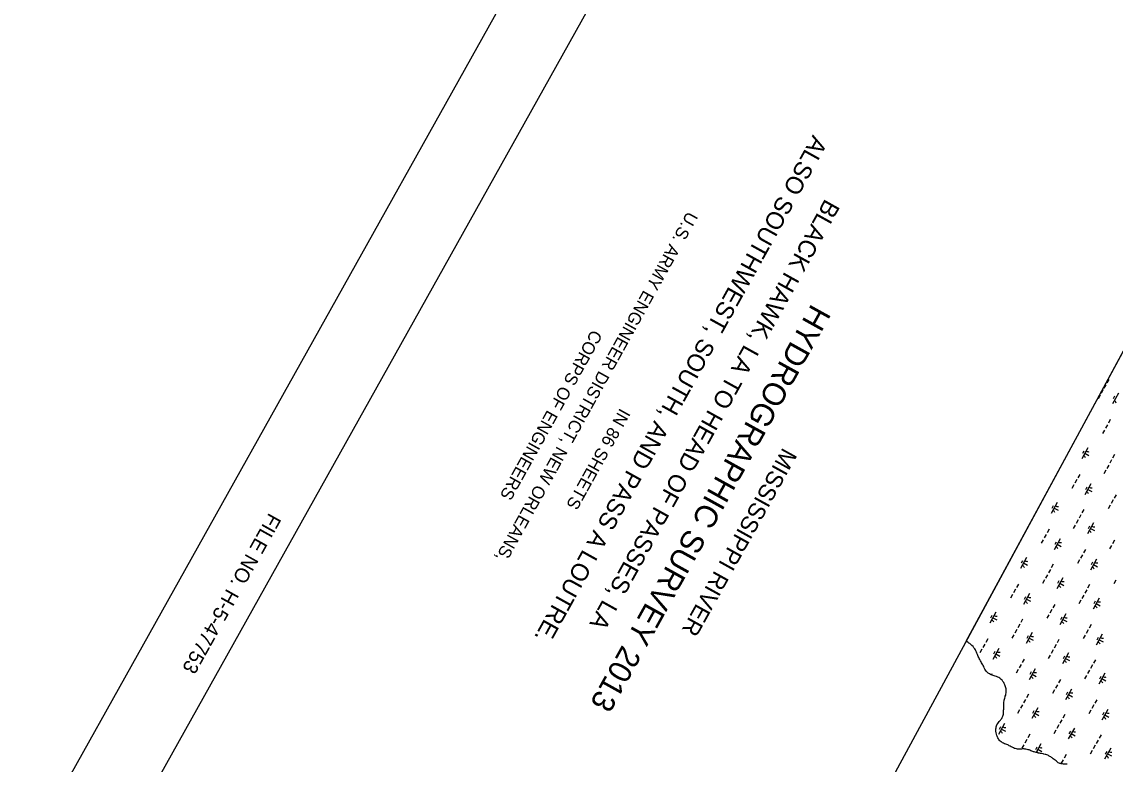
# Model space of a CAD drawing. Extents: x 3923531 to 3943530, y 207391 to 229799.
# Drawn here: x 3923785 to 3928152, y 213929 to 216895 of the extents above; entities that cross this region are included whole.
import ezdxf

# ---------------------------------------------------------------- set-up
doc = ezdxf.new("R2010")
doc.units = 0
for name, color, linetype in [('G-ANNO-NPLT', 7, 'Continuous'), ('V-ANNO-SYMB', 7, 'Continuous'), ('V-ANNO-TEXT', 7, 'Continuous'), ('V-GRID-FRAM', 7, 'Continuous'), ('V-WETL-SWMP', 7, 'Continuous')]:
    doc.layers.add(name, color=color, linetype=linetype)

msp = doc.modelspace()

# ---------------------------------------------------------------- linework, layer by layer
at = {"layer": 'G-ANNO-NPLT'}
msp.add_lwpolyline([(3932726.7, 229544.3), (3923785.3, 213539.2), (3934334.2, 207646), (3943275.5, 223651.2)], close=True, dxfattribs=at)
at = {"layer": 'V-ANNO-SYMB'}
msp.add_lwpolyline([(3932328.9, 228191.4), (3924261.4, 213750.5), (3934264.5, 208162.2), (3942332, 222603.1), (3932328.9, 228191.4)], dxfattribs=at)
at = {"layer": 'V-GRID-FRAM'}
msp.add_lwpolyline([(3941569.4, 222286.8), (3934196.5, 209089.1), (3926890.1, 213186.2), (3934009.8, 226348.1), (3941569.4, 222286.8)], dxfattribs=at)
at = {"layer": 'V-WETL-SWMP'}
for p, q in [((3927557.6, 214420.2), (3930423.1, 219717.6)), ((3928127.1, 215466.1), (3928119.3, 215452.1)), ((3928103.7, 215424.2), (3928095.9, 215410.2)), ((3928115.4, 215445.1), (3928107.6, 215431.2)), ((3928092, 215403.2), (3928084.2, 215389.3)), ((3928165.6, 215412), (3928141.3, 215368.3)), ((3928149.6, 215399.2), (3928143.8, 215388.7)), ((3928133, 215305.9), (3928125.2, 215292)), ((3928109.6, 215264), (3928101.8, 215250.1)), ((3928121.3, 215285), (3928113.5, 215271)), ((3928043.2, 215192.9), (3928018.9, 215149.3)), ((3928027.2, 215180.1), (3928021.4, 215169.6)), ((3928031.1, 215171.1), (3928046.8, 215162.3)), ((3928149.9, 215165.9), (3928142.1, 215151.9)), ((3928126.5, 215124), (3928118.7, 215110)), ((3928138.2, 215144.9), (3928130.4, 215131)), ((3928010.6, 215086.8), (3928002.8, 215072.9)), ((3928114.8, 215103), (3928107, 215089.1)), ((3927987.2, 215044.9), (3927979.4, 215031)), ((3927998.9, 215065.9), (3927991.1, 215051.9)), ((3928055.3, 215048.5), (3928030.9, 215004.8)), ((3928039.3, 215035.6), (3928033.4, 215025.2)), ((3928043.1, 215026.6), (3928058.8, 215017.9)), ((3928144.1, 214984.8), (3928136.3, 214970.8)), ((3928155.8, 215005.7), (3928148, 214991.7)), ((3927920.9, 214973.8), (3927896.5, 214930.2)), ((3927904.9, 214961), (3927899, 214950.5)), ((3927908.7, 214952), (3927924.4, 214943.2)), ((3928027.5, 214946.8), (3928019.7, 214932.8)), ((3928132.4, 214963.8), (3928124.6, 214949.8)), ((3928004.1, 214904.9), (3927996.3, 214890.9)), ((3928015.8, 214925.8), (3928008, 214911.9)), ((3927888.2, 214867.8), (3927880.4, 214853.8)), ((3927992.4, 214883.9), (3927984.6, 214870)), ((3928066.1, 214892.7), (3928041.7, 214849.1)), ((3928050.1, 214879.9), (3928044.2, 214869.4)), ((3928053.9, 214870.9), (3928069.6, 214862.1)), ((3927864.8, 214825.9), (3927857, 214811.9)), ((3927876.5, 214846.8), (3927868.7, 214832.8)), ((3927932.9, 214829.4), (3927908.5, 214785.7)), ((3927916.9, 214816.6), (3927911, 214806.1)), ((3928149.3, 214823.8), (3928141.5, 214809.8)), ((3927920.7, 214807.6), (3927936.4, 214798.8)), ((3928021.7, 214765.7), (3928013.9, 214751.7)), ((3928033.4, 214786.6), (3928025.6, 214772.7)), ((3928137.6, 214802.8), (3928129.8, 214788.8)), ((3927798.5, 214754.7), (3927774.1, 214711.1)), ((3927782.5, 214741.9), (3927776.6, 214731.4)), ((3927786.3, 214732.9), (3927802, 214724.1)), ((3927905.1, 214727.7), (3927897.3, 214713.7)), ((3928010, 214744.7), (3928002.2, 214730.8)), ((3928078.1, 214748.3), (3928053.7, 214704.6)), ((3928062.1, 214735.4), (3928056.2, 214725)), ((3928065.9, 214726.4), (3928081.6, 214717.7)), ((3927881.7, 214685.8), (3927873.9, 214671.8)), ((3927893.4, 214706.8), (3927885.6, 214692.8)), ((3927765.8, 214648.7), (3927758, 214634.7)), ((3927870, 214664.9), (3927862.2, 214650.9)), ((3927943.7, 214673.6), (3927919.3, 214630)), ((3927927.7, 214660.8), (3927921.8, 214650.3)), ((3927931.5, 214651.8), (3927947.2, 214643)), ((3928050.3, 214646.6), (3928042.5, 214632.6)), ((3928155.2, 214663.6), (3928147.4, 214649.6)), ((3927742.4, 214606.8), (3927734.6, 214592.8)), ((3927754.1, 214627.7), (3927746.3, 214613.7)), ((3927810.5, 214610.3), (3927786.1, 214566.7)), ((3927794.5, 214597.5), (3927788.6, 214587)), ((3928026.9, 214604.7), (3928019.1, 214590.7)), ((3928038.6, 214625.6), (3928030.8, 214611.7)), ((3928088.9, 214592.5), (3928064.5, 214548.8)), ((3927798.3, 214588.5), (3927814, 214579.7)), ((3927899.3, 214546.6), (3927891.5, 214532.6)), ((3927911, 214567.5), (3927903.2, 214553.6)), ((3928015.2, 214583.7), (3928007.4, 214569.8)), ((3928072.9, 214579.7), (3928067, 214569.2)), ((3928076.7, 214570.7), (3928092.4, 214561.9)), ((3927676.1, 214535.7), (3927651.7, 214492)), ((3927660.1, 214522.8), (3927654.2, 214512.4)), ((3927663.9, 214513.8), (3927679.6, 214505.1)), ((3927782.7, 214508.6), (3927774.9, 214494.7)), ((3927887.6, 214525.6), (3927879.8, 214511.7)), ((3927955.7, 214529.2), (3927931.3, 214485.5)), ((3927939.7, 214516.4), (3927933.8, 214505.9)), ((3927943.5, 214507.4), (3927959.2, 214498.6)), ((3927759.3, 214466.7), (3927751.5, 214452.8)), ((3927771, 214487.7), (3927763.2, 214473.7)), ((3928044.5, 214465.5), (3928036.7, 214451.5)), ((3928056.2, 214486.4), (3928048.4, 214472.5)), ((3927559.2, 214418.9), (3927557.6, 214420.2)), ((3927561.7, 214417.1), (3927559.2, 214418.9)), ((3927565.1, 214414.7), (3927561.7, 214417.1)), ((3927643.4, 214429.6), (3927635.6, 214415.6)), ((3927747.6, 214445.8), (3927739.8, 214431.8)), ((3927821.3, 214454.5), (3927796.9, 214410.9)), ((3927805.3, 214441.7), (3927799.4, 214431.2)), ((3927809.1, 214432.7), (3927824.8, 214423.9)), ((3927927.9, 214427.5), (3927920.1, 214413.5)), ((3928032.8, 214444.5), (3928025, 214430.5)), ((3928100.9, 214448.1), (3928076.5, 214404.4)), ((3928084.9, 214435.2), (3928079, 214424.8)), ((3928088.7, 214426.2), (3928104.4, 214417.5)), ((3927567.9, 214412.9), (3927565.1, 214414.7)), ((3927571.8, 214410.4), (3927567.9, 214412.9)), ((3927576.2, 214406.9), (3927571.8, 214410.4)), ((3927579.4, 214403.5), (3927576.2, 214406.9)), ((3927584.5, 214398.4), (3927579.4, 214403.5)), ((3927586.6, 214396), (3927584.5, 214398.4)), ((3927588.4, 214393.5), (3927586.6, 214396)), ((3927591.2, 214389.9), (3927588.4, 214393.5)), ((3927594.2, 214385.2), (3927591.2, 214389.9)), ((3927596, 214381.5), (3927594.2, 214385.2)), ((3927598.6, 214376.5), (3927596, 214381.5)), ((3927600.1, 214372.7), (3927598.6, 214376.5)), ((3927602.1, 214367.3), (3927600.1, 214372.7)), ((3927620, 214387.7), (3927612.2, 214373.7)), ((3927631.7, 214408.6), (3927623.9, 214394.7)), ((3927688.1, 214391.2), (3927663.7, 214347.6)), ((3927672.1, 214378.4), (3927666.2, 214367.9)), ((3927904.5, 214385.6), (3927896.7, 214371.6)), ((3927916.2, 214406.5), (3927908.4, 214392.6)), ((3927966.5, 214373.4), (3927942.1, 214329.8)), ((3927603.6, 214363.7), (3927602.1, 214367.3)), ((3927605.4, 214359.2), (3927603.6, 214363.7)), ((3927607.2, 214355.7), (3927605.4, 214359.2)), ((3927609.6, 214351.2), (3927607.2, 214355.7)), ((3927611.6, 214347.7), (3927609.6, 214351.2)), ((3927613.6, 214343.9), (3927611.6, 214347.7)), ((3927615.1, 214341.3), (3927613.6, 214343.9)), ((3927617, 214337.9), (3927615.1, 214341.3)), ((3927619, 214333.9), (3927617, 214337.9)), ((3927621.5, 214329.7), (3927619, 214333.9)), ((3927623.4, 214326.1), (3927621.5, 214329.7)), ((3927675.9, 214369.4), (3927691.6, 214360.6)), ((3927776.9, 214327.5), (3927769.1, 214313.5)), ((3927788.6, 214348.5), (3927780.8, 214334.5)), ((3927892.8, 214364.6), (3927885, 214350.7)), ((3927950.5, 214360.6), (3927944.6, 214350.1)), ((3927954.3, 214351.6), (3927970, 214342.8)), ((3928073.2, 214346.4), (3928065.4, 214332.4)), ((3927624.9, 214323.5), (3927623.4, 214326.1)), ((3927627.2, 214318.6), (3927624.9, 214323.5)), ((3927628.9, 214314.4), (3927627.2, 214318.6)), ((3927630.4, 214311.7), (3927628.9, 214314.4)), ((3927632.4, 214307.9), (3927630.4, 214311.7)), ((3927634.6, 214304.4), (3927632.4, 214307.9)), ((3927637.3, 214300.9), (3927634.6, 214304.4)), ((3927639.5, 214298.3), (3927637.3, 214300.9)), ((3927642.4, 214295.1), (3927639.5, 214298.3)), ((3927645, 214292.9), (3927642.4, 214295.1)), ((3927647.7, 214291.3), (3927645, 214292.9)), ((3927651, 214289.5), (3927647.7, 214291.3)), ((3927654.4, 214287.4), (3927651, 214289.5)), ((3927657.5, 214286), (3927654.4, 214287.4)), ((3927661.4, 214284.4), (3927657.5, 214286)), ((3927660.3, 214289.5), (3927658.2, 214285.7)), ((3927664.8, 214283), (3927661.4, 214284.4)), ((3927765.2, 214306.6), (3927757.4, 214292.6)), ((3927833.3, 214310.1), (3927808.9, 214266.4)), ((3927817.3, 214297.3), (3927811.4, 214286.8)), ((3927821.1, 214288.3), (3927836.8, 214279.5)), ((3928049.8, 214304.5), (3928041.9, 214290.5)), ((3928061.5, 214325.4), (3928053.7, 214311.5)), ((3928111.7, 214292.3), (3928087.3, 214248.6)), ((3927669.3, 214281.2), (3927664.8, 214283)), ((3927672.9, 214280.3), (3927669.3, 214281.2)), ((3927677.7, 214278.7), (3927672.9, 214280.3)), ((3927680.6, 214277.8), (3927677.7, 214278.7)), ((3927684, 214276.5), (3927680.6, 214277.8)), ((3927687.1, 214275.3), (3927684, 214276.5)), ((3927691.1, 214273.1), (3927687.1, 214275.3)), ((3927694.8, 214270), (3927691.1, 214273.1)), ((3927697.3, 214267.6), (3927694.8, 214270)), ((3927700.6, 214263.9), (3927697.3, 214267.6)), ((3927703.6, 214259.7), (3927700.6, 214263.9)), ((3927707.2, 214255), (3927703.6, 214259.7)), ((3927709.4, 214251.2), (3927707.2, 214255)), ((3927711.7, 214246.4), (3927709.4, 214251.2)), ((3927713.2, 214242.5), (3927711.7, 214246.4)), ((3927714.9, 214237.9), (3927713.2, 214242.5)), ((3927922.1, 214246.4), (3927914.3, 214232.4)), ((3927933.8, 214267.3), (3927926, 214253.4)), ((3928038, 214283.5), (3928030.2, 214269.6)), ((3928095.7, 214279.5), (3928089.9, 214269)), ((3928099.5, 214270.5), (3928115.2, 214261.7)), ((3927711, 214192.1), (3927712.4, 214197.3)), ((3927712.4, 214197.3), (3927713.5, 214200.9)), ((3927713.5, 214200.9), (3927715.3, 214205.1)), ((3927716, 214233.7), (3927714.9, 214237.9)), ((3927715.3, 214205.1), (3927716, 214208.7)), ((3927716.7, 214230.4), (3927716, 214233.7)), ((3927716, 214208.7), (3927716.8, 214214.1)), ((3927717.1, 214224.9), (3927716.7, 214230.4)), ((3927716.8, 214214.1), (3927717.1, 214221.7)), ((3927717.1, 214221.7), (3927717.1, 214224.9)), ((3927805.6, 214208.4), (3927797.8, 214194.4)), ((3927910.4, 214225.4), (3927902.6, 214211.5)), ((3927978.5, 214229), (3927954.1, 214185.3)), ((3927962.5, 214216.1), (3927956.7, 214205.7)), ((3927966.3, 214207.1), (3927982, 214198.4)), ((3927707, 214152.2), (3927707.4, 214156.9)), ((3927707.1, 214160.1), (3927707.4, 214165.5)), ((3927707.4, 214156.9), (3927707.1, 214160.1)), ((3927707.4, 214169.8), (3927707.8, 214172.9)), ((3927707.4, 214165.5), (3927707.4, 214169.8)), ((3927707.8, 214172.9), (3927708, 214176.5)), ((3927708, 214176.5), (3927709, 214181.8)), ((3927709, 214181.8), (3927709.5, 214185.2)), ((3927709.5, 214185.2), (3927710.2, 214188.2)), ((3927710.2, 214188.2), (3927711, 214192.1)), ((3927782.1, 214166.5), (3927774.3, 214152.5)), ((3927793.8, 214187.5), (3927786, 214173.5)), ((3927844.1, 214154.3), (3927819.7, 214110.7)), ((3928067.3, 214165.3), (3928059.5, 214151.3)), ((3928079, 214186.2), (3928071.2, 214172.2)), ((3927696.3, 214107.1), (3927699.1, 214111.8)), ((3927699.1, 214111.8), (3927701.2, 214115.8)), ((3927701.2, 214115.8), (3927703.3, 214120.6)), ((3927703.3, 214120.6), (3927704.8, 214124.7)), ((3927704.8, 214124.7), (3927705.8, 214128.8)), ((3927705.8, 214128.8), (3927706.4, 214133.3)), ((3927706.4, 214133.3), (3927706.5, 214136.5)), ((3927706.5, 214136.5), (3927706.9, 214141)), ((3927706.9, 214144.1), (3927707, 214148.6)), ((3927706.9, 214141), (3927706.9, 214144.1)), ((3927707, 214148.6), (3927707, 214152.2)), ((3927770.4, 214145.6), (3927762.6, 214131.6)), ((3927828.1, 214141.5), (3927822.2, 214131)), ((3927831.9, 214132.5), (3927847.6, 214123.7)), ((3927950.8, 214127.3), (3927943, 214113.3)), ((3928055.6, 214144.3), (3928047.8, 214130.3)), ((3928123.7, 214147.8), (3928099.3, 214104.2)), ((3928107.7, 214135), (3928101.9, 214124.5)), ((3928111.5, 214126), (3928127.2, 214117.2)), ((3927675.6, 214070.3), (3927676.4, 214073.6)), ((3927675.7, 214065.1), (3927675.6, 214070.3)), ((3927676.4, 214073.6), (3927677.3, 214078.2)), ((3927677.3, 214078.2), (3927678.2, 214081.5)), ((3927678.2, 214081.5), (3927680, 214085.9)), ((3927680, 214085.9), (3927683.1, 214091.2)), ((3927683.1, 214091.2), (3927685.8, 214095.3)), ((3927685.8, 214095.3), (3927688.4, 214098.9)), ((3927710.9, 214091), (3927686.5, 214047.4)), ((3927688.4, 214098.9), (3927690.5, 214101.3)), ((3927694.9, 214078.2), (3927689, 214067.7)), ((3927690.5, 214101.3), (3927693.8, 214104.3)), ((3927693.8, 214104.3), (3927696.3, 214107.1)), ((3927698.7, 214069.2), (3927714.4, 214060.4)), ((3927927.4, 214085.4), (3927919.6, 214071.4)), ((3927939.1, 214106.3), (3927931.3, 214092.4)), ((3927989.3, 214073.2), (3927964.9, 214029.5)), ((3927676.2, 214060.6), (3927675.7, 214065.1)), ((3927677.5, 214054.4), (3927676.2, 214060.6)), ((3927678.6, 214048.2), (3927677.5, 214054.4)), ((3927679.9, 214043.5), (3927678.6, 214048.2)), ((3927681.1, 214040.6), (3927679.9, 214043.5)), ((3927682.4, 214037.3), (3927681.1, 214040.6)), ((3927683.9, 214034.7), (3927682.4, 214037.3)), ((3927686.5, 214030), (3927683.9, 214034.7)), ((3927688, 214027.2), (3927686.5, 214030)), ((3927690.8, 214023.1), (3927688, 214027.2)), ((3927693.4, 214020.3), (3927690.8, 214023.1)), ((3927799.7, 214027.3), (3927791.9, 214013.3)), ((3927811.4, 214048.3), (3927803.6, 214034.3)), ((3927915.7, 214064.4), (3927907.8, 214050.5)), ((3927973.3, 214060.4), (3927967.5, 214049.9)), ((3927977.1, 214051.4), (3927992.8, 214042.6)), ((3928084.3, 214025.2), (3928076.5, 214011.2)), ((3928096, 214046.2), (3928088.2, 214032.2)), ((3927696.6, 214018.2), (3927693.4, 214020.3)), ((3927699.9, 214016.2), (3927696.6, 214018.2)), ((3927702.8, 214014.7), (3927699.9, 214016.2)), ((3927706, 214012.5), (3927702.8, 214014.7)), ((3927709.8, 214010.6), (3927706, 214012.5)), ((3927711.5, 214009.7), (3927709.8, 214010.6)), ((3927719.9, 214007), (3927711.5, 214009.7)), ((3927723.2, 214005.8), (3927719.9, 214007)), ((3927725.9, 214004.5), (3927723.2, 214005.8)), ((3927729.3, 214002.4), (3927725.9, 214004.5)), ((3927733.1, 214000.5), (3927729.3, 214002.4)), ((3927736.8, 213998.4), (3927733.1, 214000.5)), ((3927740.6, 213996.9), (3927736.8, 213998.4)), ((3927743.4, 213995.7), (3927740.6, 213996.9)), ((3927746.6, 213993.8), (3927743.4, 213995.7)), ((3927750.5, 213992), (3927746.6, 213993.8)), ((3927753.5, 213990.9), (3927750.5, 213992)), ((3927758.3, 213989.8), (3927753.5, 213990.9)), ((3927762.9, 213989.1), (3927758.3, 213989.8)), ((3927766.9, 213988.7), (3927762.9, 213989.1)), ((3927770.3, 213988.8), (3927766.9, 213988.7)), ((3927774.1, 213988.9), (3927770.3, 213988.8)), ((3927777.9, 213989.4), (3927774.1, 213988.9)), ((3927781.7, 213989.7), (3927777.9, 213989.4)), ((3927788, 214006.3), (3927780.2, 213992.4)), ((3927785.1, 213989.8), (3927781.7, 213989.7)), ((3927788.6, 213989.8), (3927785.1, 213989.8)), ((3927791.8, 213989.2), (3927788.6, 213989.8)), ((3927796.1, 213988.3), (3927791.8, 213989.2)), ((3927800.4, 213987.4), (3927796.1, 213988.3)), ((3927804.7, 213986.4), (3927800.4, 213987.4)), ((3927808.8, 213985.5), (3927804.7, 213986.4)), ((3927812.1, 213984.1), (3927808.8, 213985.5)), ((3927816, 213982.2), (3927812.1, 213984.1)), ((3927819.6, 213980.6), (3927816, 213982.2)), ((3927822.9, 213979.3), (3927819.6, 213980.6)), ((3927826, 213978.1), (3927822.9, 213979.3)), ((3927829.1, 213977.5), (3927826, 213978.1)), ((3927840.1, 213997.1), (3927834.3, 213986.6)), ((3927856.1, 214009.9), (3927837, 213975.7)), ((3927843.9, 213988.1), (3927859.6, 213979.3)), ((3928060.9, 213983.3), (3928053.1, 213969.3)), ((3928072.6, 214004.3), (3928064.8, 213990.3)), ((3928134.5, 213992.1), (3928110.1, 213948.4)), ((3928118.5, 213979.3), (3928112.7, 213968.8)), ((3927832.8, 213976.6), (3927829.1, 213977.5)), ((3927837, 213975.7), (3927832.8, 213976.6)), ((3927841.8, 213974.4), (3927837, 213975.7)), ((3927846.6, 213973.3), (3927841.8, 213974.4)), ((3927849.7, 213972.8), (3927846.6, 213973.3)), ((3927853.8, 213971.7), (3927849.7, 213972.8)), ((3927858.4, 213970.9), (3927853.8, 213971.7)), ((3927864.1, 213969.8), (3927858.4, 213970.9)), ((3927867.7, 213969.1), (3927864.1, 213969.8)), ((3927872.7, 213968), (3927867.7, 213969.1)), ((3927875.8, 213967.2), (3927872.7, 213968)), ((3927878.8, 213965.8), (3927875.8, 213967.2)), ((3927882.8, 213964.2), (3927878.8, 213965.8)), ((3927885.9, 213963), (3927882.8, 213964.2)), ((3927889.3, 213961), (3927885.9, 213963)), ((3927891.9, 213959.4), (3927889.3, 213961)), ((3927894.8, 213957.7), (3927891.9, 213959.4)), ((3927898.3, 213955.2), (3927894.8, 213957.7)), ((3927901.1, 213953.5), (3927898.3, 213955.2)), ((3927905.3, 213950.1), (3927901.1, 213953.5)), ((3927908.6, 213947.9), (3927905.3, 213950.1)), ((3927912.3, 213944.9), (3927908.6, 213947.9)), ((3927916.2, 213941.6), (3927912.3, 213944.9)), ((3927918.8, 213939.3), (3927916.2, 213941.6)), ((3927921.7, 213937), (3927918.8, 213939.3)), ((3927925.1, 213934.7), (3927921.7, 213937)), ((3927928.2, 213933.1), (3927925.1, 213934.7)), ((3927944.9, 213946.2), (3927937.1, 213932.2)), ((3927956.7, 213967.1), (3927948.8, 213953.2)), ((3928122.3, 213970.3), (3928138.1, 213961.5)), ((3927931.1, 213931.9), (3927928.2, 213933.1)), ((3927934, 213931.2), (3927931.1, 213931.9)), ((3927937.3, 213930.3), (3927934, 213931.2)), ((3927941.4, 213929.5), (3927937.3, 213930.3)), ((3927946.2, 213929.1), (3927941.4, 213929.5)), ((3927951.2, 213929.2), (3927946.2, 213929.1)), ((3927956.4, 213929), (3927951.2, 213929.2)), ((3927961.2, 213928.9), (3927956.4, 213929))]:
    msp.add_line(p, q, dxfattribs=at)
for centre, start, end in [((3928140.2, 215365.9), 20.0381, 61.5817), ((3928017.8, 215146.9), 20.0381, 61.5817), ((3928044.7, 215195.1), 240.0381, 281.5817), ((3928056.7, 215050.6), 240.0381, 281.5817), ((3928029.8, 215002.4), 20.0381, 61.5817), ((3927895.4, 214927.8), 20.0381, 61.5817), ((3927922.3, 214976), 240.0381, 281.5817), ((3928040.6, 214846.6), 20.0381, 61.5817), ((3928067.6, 214894.9), 240.0381, 281.5817), ((3927934.4, 214831.6), 240.0381, 281.5817), ((3927907.4, 214783.3), 20.0381, 61.5817), ((3927773, 214708.7), 20.0381, 61.5817), ((3927799.9, 214756.9), 240.0381, 281.5817), ((3928079.6, 214750.4), 240.0381, 281.5817), ((3928052.6, 214702.2), 20.0381, 61.5817), ((3927918.2, 214627.6), 20.0381, 61.5817), ((3927945.2, 214675.8), 240.0381, 281.5817), ((3927812, 214612.5), 240.0381, 281.5817), ((3927785, 214564.2), 20.0381, 61.5817), ((3928063.4, 214546.4), 20.0381, 61.5817), ((3928090.4, 214594.7), 240.0381, 281.5817), ((3927650.6, 214489.6), 20.0381, 61.5817), ((3927677.6, 214537.8), 240.0381, 281.5817), ((3927957.2, 214531.4), 240.0381, 281.5817), ((3927930.2, 214483.1), 20.0381, 61.5817), ((3927795.8, 214408.5), 20.0381, 61.5817), ((3927822.8, 214456.7), 240.0381, 281.5817), ((3928075.4, 214402), 20.0381, 61.5817), ((3928102.4, 214450.2), 240.0381, 281.5817), ((3927689.6, 214393.4), 240.0381, 281.5817), ((3927662.6, 214345.2), 20.0381, 61.5817), ((3927941, 214327.4), 20.0381, 61.5817), ((3927968, 214375.6), 240.0381, 281.5817), ((3927834.8, 214312.3), 240.0381, 281.5817), ((3927807.8, 214264), 20.0381, 61.5817), ((3928086.3, 214246.2), 20.0381, 61.5817), ((3928113.2, 214294.5), 240.0381, 281.5817), ((3927953.1, 214182.9), 20.0381, 61.5817), ((3927980, 214231.1), 240.0381, 281.5817), ((3927818.6, 214108.3), 20.0381, 61.5817), ((3927845.6, 214156.5), 240.0381, 281.5817), ((3928098.3, 214101.8), 20.0381, 61.5817), ((3928125.2, 214150), 240.0381, 281.5817), ((3927712.4, 214093.2), 240.0381, 281.5817), ((3927685.4, 214045), 20.0381, 61.5817), ((3927963.9, 214027.1), 20.0381, 61.5817), ((3927990.8, 214075.4), 240.0381, 281.5817), ((3927830.7, 213963.8), 33.6317, 61.5817), ((3927857.6, 214012.1), 240.0381, 281.5817), ((3928136, 213994.2), 240.0381, 281.5817), ((3928109.1, 213946), 20.0381, 61.5817)]:
    msp.add_arc(centre, 17.6, start, end, dxfattribs=at)

# ---------------------------------------------------------------- texts
at = {"layer": 'V-ANNO-TEXT'}
for s, height, rotation, p in [('ALSO SOUTHWEST, SOUTH, AND PASS A LOUTRE.', 70, 240.9857, (3926944.9, 216446)), ('BLACK HAWK, LA TO HEAD OF PASSES, LA', 70, 240.9857, (3926994.3, 216191.1)), ('U.S. ARMY ENGINEER DISTRICT, NEW ORLEANS,', 50, 240.9857, (3926444.1, 216140.8)), ('HYDROGRAPHIC SURVEY 2013', 90.85, 240.9857, (3926940.4, 215772)), ('CORPS OF ENGINEERS', 50, 240.9857, (3926062.9, 215668.4)), ('IN 86 SHEETS', 50, 240.9857, (3926174.6, 215354.4)), ('MISSISSIPPI RIVER', 67.5, 240.9857, (3926825.5, 215197)), ('FILE NO. H-5-47753', 58.33, 240.8099, (3924773.1, 214936.2))]:
    msp.add_text(s, height=height, rotation=rotation, dxfattribs=at).set_placement(p)

doc.saveas('drawing.dxf')
